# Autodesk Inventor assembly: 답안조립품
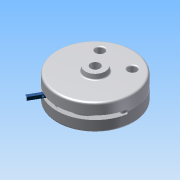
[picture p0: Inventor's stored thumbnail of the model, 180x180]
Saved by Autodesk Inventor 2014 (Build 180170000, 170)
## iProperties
Created: 2015-06
Part Number: 답안조립품
Document SubType Name: Assembly
Designer: Administrator
Author: Administrator
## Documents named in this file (9)
- C:\Documents and Settings\Administrator\바탕 화면\450631V1026\답안조립품.iam
- C:\Documents and Settings\Administrator\바탕 화면\450631V1026\1-본체.ipt
- C:\Documents and Settings\Administrator\바탕 화면\450631V1026\베어링62_22.ipt
- C:\Documents and Settings\Administrator\바탕 화면\450631V1026\축.ipt
- C:\Documents and Settings\Administrator\바탕 화면\450631V1026\멈춤링.ipt
- C:\Documents and Settings\Administrator\바탕 화면\450631V1026\슬라이더2.ipt
- C:\Documents and Settings\Administrator\바탕 화면\450631V1026\슬라이더.ipt
- C:\Documents and Settings\Administrator\바탕 화면\450631V1026\평행핀.ipt
- C:\Documents and Settings\Administrator\바탕 화면\450631V1026\덮개.ipt
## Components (6 placed, 4 different names)
1. 1-본체:1
2. KS B 2023 62/22 - 22 x 50 x 14:1 — 플러쉬:6
3. KS B 1336 22 x 1.2:1 — 플러쉬:6
4. KS B 1336 22 x 1.2:2
5. KS B 1320 B B 5 x  20:1
6. KS B 2023 62/22 - 22 x 50 x 14:2
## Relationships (1: Flush 1)
- 플러쉬:6 [Flush]: KS B 2023 62/22 - 22 x 50 x 14:1 ↔ KS B 1336 22 x 1.2:1
